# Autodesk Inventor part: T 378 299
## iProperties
Company: Mayer & Müller AG Schaltgeräte
Created: 2006-10
Part Number: T 378 299
Material: Hm 2472
Document SubType Name: Modeling
Designer: I.Baliuc
Manufacturer: Standard
Standards Organization: Custom
Description: Isolierplatte
Density: 0.94 g/cm^3
HalbzeugNorm: Gatex Typ 1290
Abmessung: EN 60893
Author: T.Messerschmitt
Comments: EN 60893 UP GM 203 Gatex Typ 1290 weiß
Revision Number: 378299
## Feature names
1. Extrusion2
